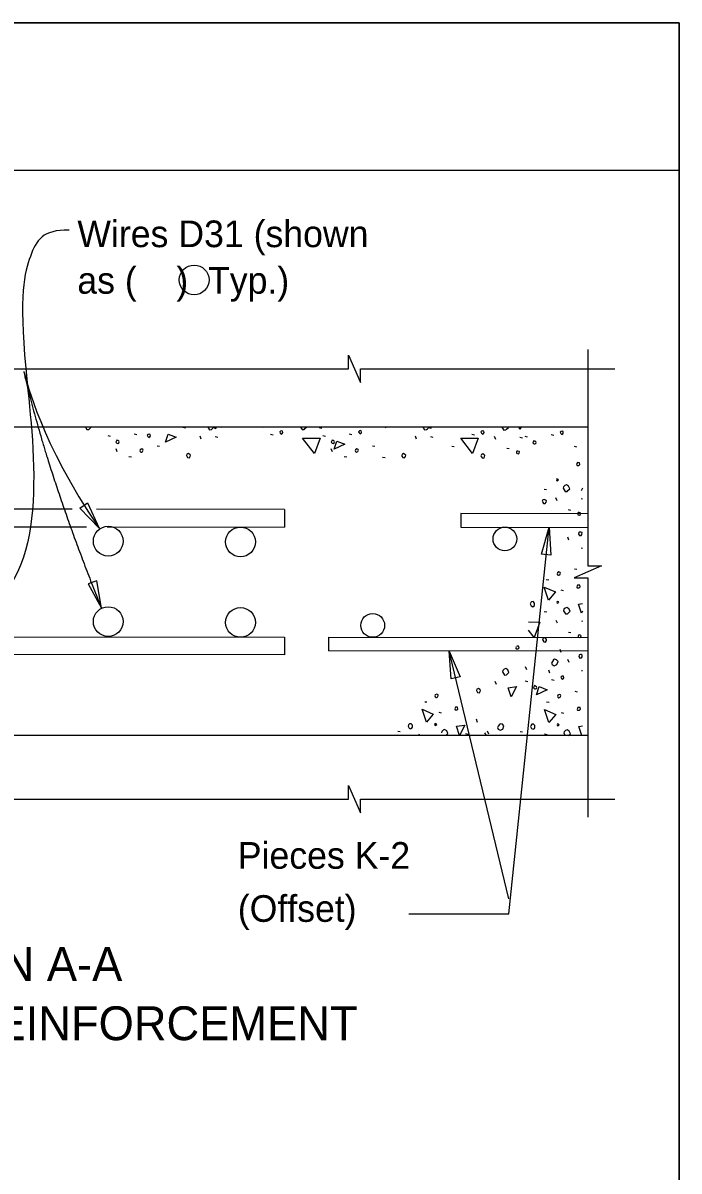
# Model space of a CAD drawing. Extents: x 0 to 20.5, y 0 to 13.
# Drawn here: x 18.052 to 20.533, y 8.632 to 12.973 of the extents above; entities that cross this region are included whole.
import ezdxf

# ---------------------------------------------------------------- set-up
doc = ezdxf.new("R2010")
doc.units = 0
for name, color, linetype in [('ActivePts-ConstElements', 7, 'Continuous'), ('BeamConc', 7, 'Continuous'), ('Dimension', 7, 'Continuous'), ('Miscellaneous', 7, 'Continuous'), ('Miscellaneous1', 7, 'Continuous'), ('Rebar', 7, 'Continuous'), ('Rebar_h', 7, 'Continuous')]:
    doc.layers.add(name, color=color, linetype=linetype)

msp = doc.modelspace()

# ---------------------------------------------------------------- linework, layer by layer
at = {"layer": 'ActivePts-ConstElements'}
msp.add_lwpolyline([(0, 0), (20.5333, 0), (20.5333, 12.9731), (0, 12.9731)], close=True, dxfattribs=at)
at = {"layer": 'BeamConc'}
for p, q in [((20.1882, 11.4449), (16.0404, 11.4449)), ((20.1882, 10.2782), (16.0404, 10.2782))]:
    msp.add_line(p, q, dxfattribs=at)
at = {"layer": 'Dimension'}
for p, q in [((0, 12.4165), (20.5333, 12.4165)), ((19.8892, 9.6606), (19.6674, 10.5821))]:
    msp.add_line(p, q, dxfattribs=at)
for points in [[(20.1882, 11.7379), (20.1882, 10.9199), (20.2398, 10.9199), (20.1882, 10.8974), (20.1365, 10.8749), (20.1882, 10.8749), (20.1882, 9.9704)], [(17.8713, 11.6648), (19.2832, 11.6648), (19.2832, 11.7165), (19.3057, 11.6648), (19.3282, 11.6131), (19.3282, 11.6648), (20.2903, 11.6648)], [(19.5119, 9.6044), (19.8892, 9.6044), (20.0416, 11.0659)], [(17.9336, 10.0376), (19.2832, 10.0376), (19.2832, 10.0893), (19.3057, 10.0376), (19.3282, 9.986), (19.3282, 10.0376), (20.2903, 10.0376)]]:
    msp.add_lwpolyline(points, dxfattribs=at)
for points in [[(18.2961, 11.1587), (18.3402, 11.0627), (18.267, 11.1388)], [(20.0132, 10.9641), (20.0416, 11.0659), (20.0483, 10.9605)], [(18.3492, 10.7599), (18.3317, 10.8641), (18.2984, 10.8525)], [(19.671, 10.4925), (19.6638, 10.5979), (19.7053, 10.5007)]]:
    msp.add_lwpolyline(points, close=True, dxfattribs=at)
for points, degree in [([(18.2263, 12.1894), (18.1269, 12.1921), (18.0784, 12.1111), (18.0162, 11.8657), (18.1616, 10.9078), (17.9075, 10.7552)], 3), ([(18.0553, 11.6549), (18.141, 11.2789), (18.3492, 10.7599)], 2), ([(18.0557, 11.6533), (18.0712, 11.6093), (18.1147, 11.3932), (18.3402, 11.0627)], 3)]:
    msp.add_open_spline(points, degree=degree, dxfattribs=at)
at = {"layer": 'Miscellaneous'}
for p, q in [((18.4453, 11.4435), (18.4448, 11.4449)), ((18.4724, 11.4188), (18.4824, 11.417)), ((18.6568, 11.4441), (18.6669, 11.4423)), ((18.9613, 11.4423), (18.9603, 11.4449)), ((18.9883, 11.4176), (18.9984, 11.4158)), ((19.1728, 11.4429), (19.1828, 11.4411)), ((19.2864, 11.4188), (19.2964, 11.417)), ((19.4244, 11.4411), (19.423, 11.4449)), ((19.7495, 11.4176), (19.7595, 11.4158)), ((18.3729, 11.4134), (18.3823, 11.4111)), ((18.5602, 11.3746), (18.569, 11.3728)), ((18.7264, 11.3993), (18.7222, 11.4105)), ((18.7792, 11.4093), (18.7887, 11.407)), ((19.1868, 11.4134), (19.1963, 11.4111)), ((19.3742, 11.3746), (19.383, 11.3728)), ((19.5404, 11.3993), (19.5362, 11.4105)), ((19.5932, 11.4093), (19.6027, 11.407)), ((19.84, 11.3981), (19.8359, 11.4093)), ((19.9314, 11.407), (19.9408, 11.4046)), ((19.9496, 11.4111), (19.959, 11.4087)), ((20.0492, 11.4164), (20.0592, 11.4146)), ((18.4082, 11.351), (18.4041, 11.3622)), ((18.4524, 11.3339), (18.463, 11.3327)), ((19.2222, 11.351), (19.2181, 11.3622)), ((19.2664, 11.3339), (19.277, 11.3327)), ((19.4114, 11.3315), (19.422, 11.3304)), ((19.6739, 11.3734), (19.6827, 11.3716)), ((19.8825, 11.3651), (19.8913, 11.3634)), ((20.137, 11.3722), (20.1458, 11.3704)), ((20.0227, 11.2108), (20.0327, 11.209)), ((20.0722, 11.166), (20.068, 11.1772)), ((20.1635, 11.1748), (20.1686, 11.1736)), ((20.1146, 11.133), (20.1234, 11.1312)), ((20.1169, 11.0175), (20.1122, 11.0293)), ((20.1629, 10.9881), (20.1686, 10.9873)), ((20.1381, 10.9091), (20.147, 10.9074)), ((20.0303, 10.8685), (20.0409, 10.8673)), ((20.0863, 10.829), (20.0957, 10.8266)), ((20.0239, 10.7477), (20.0339, 10.7459)), ((20.0734, 10.7029), (20.0692, 10.7141)), ((20.1647, 10.7118), (20.1686, 10.7108)), ((20.1158, 10.6699), (20.1246, 10.6682)), ((20.0881, 10.5927), (20.0834, 10.6045)), ((20.1181, 10.5545), (20.1134, 10.5662)), ((19.9578, 10.5266), (19.953, 10.5384)), ((20.0445, 10.5149), (20.0404, 10.5261)), ((20.1641, 10.525), (20.1686, 10.5244)), ((19.8424, 10.472), (19.8383, 10.4832)), ((19.952, 10.4849), (19.9614, 10.4825)), ((20.0515, 10.4902), (20.0615, 10.4885)), ((20.1393, 10.446), (20.1482, 10.4443)), ((19.5726, 10.4061), (19.579, 10.4054)), ((20.0315, 10.4054), (20.0421, 10.4042)), ((19.6244, 10.3671), (19.6338, 10.3647)), ((19.7717, 10.3282), (19.767, 10.34)), ((20.0875, 10.3659), (20.0969, 10.3635)), ((19.47, 10.2952), (19.4783, 10.294)), ((19.8135, 10.284), (19.8094, 10.2952)), ((19.9331, 10.294), (19.9414, 10.2929)), ((19.7254, 10.2858), (19.7354, 10.284)), ((20.025, 10.2846), (20.035, 10.2829))]:
    msp.add_line(p, q, dxfattribs=at)
for points in [[(18.2884, 11.4449), (18.2939, 11.4358), (18.3016, 11.4364), (18.3045, 11.4394), (18.31, 11.4449)], [(18.5247, 11.4091), (18.5283, 11.4056), (18.5318, 11.408), (18.5341, 11.4115), (18.533, 11.4174), (18.53, 11.418), (18.5259, 11.4174), (18.5224, 11.4139), (18.5247, 11.4091)], [(18.5914, 11.3881), (18.6008, 11.4187), (18.632, 11.4064), (18.5914, 11.3881)], [(18.7507, 11.4449), (18.757, 11.4347), (18.7647, 11.4353), (18.7676, 11.4382), (18.7741, 11.4447), (18.774, 11.4449)], [(18.7792, 11.4388), (18.7772, 11.4449)], [(18.7823, 11.4449), (18.7792, 11.4388)], [(18.7956, 11.444), (18.7953, 11.4449)], [(18.8014, 11.4449), (18.8001, 11.4423)], [(19.0255, 11.4217), (19.029, 11.4182), (19.0325, 11.4205), (19.0349, 11.4241), (19.0337, 11.4299), (19.0308, 11.4305), (19.0266, 11.4299), (19.0231, 11.4264), (19.0255, 11.4217)], [(19.1023, 11.4449), (19.1079, 11.4358), (19.1156, 11.4364), (19.1185, 11.4394), (19.124, 11.4449)], [(19.3235, 11.4229), (19.3271, 11.4193), (19.3306, 11.4217), (19.3329, 11.4252), (19.3318, 11.4311), (19.3288, 11.4317), (19.3247, 11.4311), (19.3212, 11.4276), (19.3235, 11.4229)], [(19.5647, 11.4449), (19.571, 11.4347), (19.5787, 11.4353), (19.5816, 11.4382), (19.5881, 11.4447), (19.588, 11.4449)], [(19.5932, 11.4388), (19.5912, 11.4449)], [(19.5963, 11.4449), (19.5932, 11.4388)], [(19.7866, 11.4217), (19.7901, 11.4182), (19.7937, 11.4205), (19.796, 11.4241), (19.7949, 11.4299), (19.7919, 11.4305), (19.7878, 11.4299), (19.7842, 11.4264), (19.7866, 11.4217)], [(19.8636, 11.4449), (19.8707, 11.4335), (19.8783, 11.4341), (19.8813, 11.437), (19.8878, 11.4435), (19.8872, 11.4449)], [(19.9313, 11.4364), (19.9286, 11.4449)], [(19.9357, 11.4449), (19.9313, 11.4364)], [(20.0863, 11.4205), (20.0898, 11.417), (20.0933, 11.4193), (20.0957, 11.4229), (20.0945, 11.4288), (20.0916, 11.4294), (20.0875, 11.4288), (20.0839, 11.4252), (20.0863, 11.4205)], [(18.407, 11.384), (18.4112, 11.3834), (18.4153, 11.3851), (18.4165, 11.3887), (18.4147, 11.3916), (18.4112, 11.394), (18.407, 11.3957), (18.4047, 11.391), (18.4035, 11.3875), (18.407, 11.384)], [(19.1545, 11.3445), (19.1097, 11.4034), (19.1763, 11.4028), (19.1545, 11.3445)], [(19.221, 11.384), (19.2252, 11.3834), (19.2293, 11.3851), (19.2305, 11.3887), (19.2287, 11.3916), (19.2252, 11.394), (19.221, 11.3957), (19.2187, 11.391), (19.2175, 11.3875), (19.221, 11.384)], [(19.2292, 11.3616), (19.2387, 11.3922), (19.2699, 11.3799), (19.2292, 11.3616)], [(19.7522, 11.3445), (19.7075, 11.4034), (19.774, 11.4028), (19.7522, 11.3445)], [(19.9838, 11.3816), (19.9879, 11.381), (19.992, 11.3828), (19.9932, 11.3863), (19.9914, 11.3893), (19.9879, 11.3916), (19.9838, 11.3934), (19.9814, 11.3887), (19.9802, 11.3851), (19.9838, 11.3816)], [(18.4977, 11.3498), (18.5001, 11.3498), (18.5048, 11.3522), (18.5066, 11.3575), (18.506, 11.3604), (18.5013, 11.3628), (18.4954, 11.3592), (18.4942, 11.3557), (18.4954, 11.3522), (18.4977, 11.3498)], [(18.6716, 11.3351), (18.6745, 11.3298), (18.6816, 11.3286), (18.6845, 11.3339), (18.6857, 11.3386), (18.6828, 11.3416), (18.6775, 11.3445), (18.6722, 11.3427), (18.6704, 11.3374), (18.6716, 11.3351)], [(19.3117, 11.3498), (19.3141, 11.3498), (19.3188, 11.3522), (19.3206, 11.3575), (19.32, 11.3604), (19.3153, 11.3628), (19.3094, 11.3592), (19.3082, 11.3557), (19.3094, 11.3522), (19.3117, 11.3498)], [(19.4856, 11.3351), (19.4885, 11.3298), (19.4956, 11.3286), (19.4985, 11.3339), (19.4997, 11.3386), (19.4968, 11.3416), (19.4915, 11.3445), (19.4862, 11.3427), (19.4844, 11.3374), (19.4856, 11.3351)], [(19.7852, 11.3339), (19.7882, 11.3286), (19.7953, 11.3274), (19.7982, 11.3327), (19.7994, 11.3374), (19.7964, 11.3404), (19.7911, 11.3433), (19.7858, 11.3416), (19.7841, 11.3363), (19.7852, 11.3339)], [(19.9184, 11.3457), (19.9249, 11.3439), (19.929, 11.3469), (19.9296, 11.351), (19.9284, 11.3522), (19.9237, 11.3545), (19.9196, 11.3539), (19.919, 11.3498), (19.9184, 11.3457)], [(20.1476, 11.3003), (20.1546, 11.3003), (20.1582, 11.3038), (20.1564, 11.3103), (20.1487, 11.3109), (20.1476, 11.3074), (20.1458, 11.3044), (20.1476, 11.3003), (20.1464, 11.3015)], [(20.0716, 11.242), (20.0781, 11.245), (20.0757, 11.2473), (20.0716, 11.2491), (20.0698, 11.245), (20.0716, 11.242)], [(20.0952, 11.2137), (20.1028, 11.2014), (20.1105, 11.2019), (20.1134, 11.2049), (20.1199, 11.2114), (20.1158, 11.2214), (20.1075, 11.2261), (20.1016, 11.2237), (20.0969, 11.219), (20.0952, 11.2137)], [(20.1686, 11.2142), (20.1635, 11.2043)], [(20.0174, 11.1619), (20.0203, 11.1566), (20.0274, 11.1554), (20.0303, 11.1608), (20.0315, 11.1655), (20.0286, 11.1684), (20.0233, 11.1714), (20.018, 11.1696), (20.0162, 11.1643), (20.0174, 11.1619)], [(20.1505, 11.1136), (20.157, 11.1118), (20.1612, 11.1147), (20.1617, 11.1189), (20.1606, 11.12), (20.1558, 11.1224), (20.1517, 11.1218), (20.1511, 11.1177), (20.1505, 11.1136)], [(20.1535, 11.0399), (20.1564, 11.0346), (20.1629, 11.0352), (20.1658, 11.0393), (20.1664, 11.0458), (20.1623, 11.0476), (20.1593, 11.0482), (20.1558, 11.047), (20.1546, 11.0458), (20.1535, 11.0399)], [(20.0757, 10.8844), (20.078, 10.8844), (20.0827, 10.8867), (20.0845, 10.892), (20.0839, 10.895), (20.0792, 10.8973), (20.0733, 10.8938), (20.0721, 10.8903), (20.0733, 10.8867), (20.0757, 10.8844)], [(20.0398, 10.7907), (20.0239, 10.8396), (20.0657, 10.8214), (20.0398, 10.7907)], [(20.1487, 10.8372), (20.1558, 10.8372), (20.1593, 10.8408), (20.1576, 10.8472), (20.1499, 10.8478), (20.1487, 10.8443), (20.147, 10.8414), (20.1487, 10.8372), (20.1476, 10.8384)], [(19.9708, 10.776), (19.9744, 10.7689), (19.9802, 10.7654), (19.985, 10.7689), (19.9873, 10.7725), (19.9873, 10.7795), (19.982, 10.7848), (19.9755, 10.7842), (19.9726, 10.7813), (19.9708, 10.776)], [(20.0728, 10.7789), (20.0792, 10.7819), (20.0769, 10.7842), (20.0728, 10.786), (20.071, 10.7819), (20.0728, 10.7789)], [(20.1646, 10.7412), (20.1535, 10.7759), (20.1686, 10.7779)], [(20.0963, 10.7506), (20.104, 10.7383), (20.1117, 10.7389), (20.1146, 10.7418), (20.1211, 10.7483), (20.117, 10.7583), (20.1087, 10.763), (20.1028, 10.7607), (20.0981, 10.756), (20.0963, 10.7506)], [(20.1686, 10.7488), (20.1646, 10.7412)], [(19.9646, 10.708), (20.0074, 10.7076), (19.9856, 10.6493)], [(19.9856, 10.6493), (19.9645, 10.677)], [(20.0186, 10.6387), (20.0215, 10.6334), (20.0286, 10.6322), (20.0315, 10.6375), (20.0327, 10.6422), (20.0297, 10.6452), (20.0244, 10.6481), (20.0191, 10.6463), (20.0174, 10.641), (20.0186, 10.6387)], [(20.1517, 10.6505), (20.1582, 10.6487), (20.1623, 10.6517), (20.1629, 10.6558), (20.1617, 10.657), (20.157, 10.6593), (20.1529, 10.6587), (20.1523, 10.6546), (20.1517, 10.6505)], [(19.918, 10.6141), (19.9178, 10.6134), (19.916, 10.6104), (19.9178, 10.6063), (19.9166, 10.6075)], [(19.9178, 10.6063), (19.9249, 10.6063), (19.9284, 10.6098), (19.9266, 10.6163), (19.9202, 10.6168)], [(20.0539, 10.5468), (20.0616, 10.5426), (20.0716, 10.5468), (20.0757, 10.5591), (20.0698, 10.565), (20.0622, 10.5668), (20.0586, 10.5644), (20.0545, 10.558), (20.0515, 10.5527), (20.0539, 10.5468)], [(20.1546, 10.5769), (20.1576, 10.5716), (20.1641, 10.5721), (20.167, 10.5763), (20.1676, 10.5827), (20.1635, 10.5845), (20.1605, 10.5851), (20.157, 10.5839), (20.1558, 10.5827), (20.1546, 10.5769)], [(19.8654, 10.5197), (19.873, 10.5073), (19.8807, 10.5079), (19.8836, 10.5109), (19.8901, 10.5173), (19.886, 10.5274), (19.8778, 10.5321), (19.8719, 10.5297), (19.8671, 10.525), (19.8654, 10.5197)], [(19.898, 10.4246), (19.8869, 10.4593), (19.9181, 10.4635), (19.898, 10.4246)], [(19.9861, 10.4554), (19.9903, 10.4548), (19.9944, 10.4566), (19.9956, 10.4601), (19.9938, 10.4631), (19.9903, 10.4654), (19.9861, 10.4672), (19.9838, 10.4625), (19.9826, 10.459), (19.9861, 10.4554)], [(19.9944, 10.4331), (20.0038, 10.4637), (20.035, 10.4513), (19.9944, 10.4331)], [(20.0886, 10.4944), (20.0922, 10.4908), (20.0957, 10.4932), (20.0981, 10.4967), (20.0969, 10.5026), (20.0939, 10.5032), (20.0898, 10.5026), (20.0863, 10.4991), (20.0886, 10.4944)], [(19.6138, 10.4225), (19.6161, 10.4225), (19.6208, 10.4248), (19.6226, 10.4301), (19.622, 10.4331), (19.6173, 10.4354), (19.6114, 10.4319), (19.6102, 10.4284), (19.6114, 10.4248), (19.6138, 10.4225)], [(19.7686, 10.4466), (19.7716, 10.4413), (19.7787, 10.4401), (19.7816, 10.4454), (19.7828, 10.4501), (19.7798, 10.4531), (19.7745, 10.456), (19.7692, 10.4542), (19.7675, 10.4489), (19.7686, 10.4466)], [(20.0769, 10.4213), (20.0792, 10.4213), (20.0839, 10.4236), (20.0857, 10.429), (20.0851, 10.4319), (20.0804, 10.4343), (20.0745, 10.4307), (20.0733, 10.4272), (20.0745, 10.4236), (20.0769, 10.4213)], [(19.5779, 10.3288), (19.562, 10.3777), (19.6038, 10.3595), (19.5779, 10.3288)], [(19.6868, 10.3753), (19.6939, 10.3753), (19.6974, 10.3789), (19.6957, 10.3853), (19.688, 10.3859), (19.6868, 10.3824), (19.6851, 10.3795), (19.6868, 10.3753), (19.6857, 10.3765)], [(20.0409, 10.3276), (20.025, 10.3765), (20.0669, 10.3583), (20.0409, 10.3276)], [(20.1499, 10.3742), (20.157, 10.3742), (20.1605, 10.3777), (20.1588, 10.3842), (20.1511, 10.3848), (20.1499, 10.3812), (20.1482, 10.3783), (20.1499, 10.3742), (20.1487, 10.3753)], [(19.5089, 10.3141), (19.5125, 10.307), (19.5183, 10.3035), (19.5231, 10.307), (19.5254, 10.3105), (19.5254, 10.3176), (19.5201, 10.3229), (19.5136, 10.3223), (19.5107, 10.3194), (19.5089, 10.3141)], [(19.6109, 10.317), (19.6173, 10.32), (19.615, 10.3223), (19.6109, 10.3241), (19.6091, 10.32), (19.6109, 10.317)], [(19.6521, 10.2793), (19.6527, 10.2799), (19.6592, 10.2864), (19.6551, 10.2964), (19.6468, 10.3011), (19.6409, 10.2988), (19.6362, 10.294), (19.6344, 10.2887)], [(19.7027, 10.2793), (19.6916, 10.314), (19.7228, 10.3182), (19.7027, 10.2793)], [(19.8492, 10.303), (19.8569, 10.2989), (19.8669, 10.303), (19.871, 10.3154), (19.8651, 10.3212), (19.8575, 10.323), (19.8539, 10.3207), (19.8498, 10.3142), (19.8469, 10.3089), (19.8492, 10.303)], [(19.972, 10.3129), (19.9755, 10.3058), (19.9814, 10.3023), (19.9861, 10.3058), (19.9885, 10.3094), (19.9885, 10.3164), (19.9832, 10.3217), (19.9767, 10.3212), (19.9738, 10.3182), (19.972, 10.3129)], [(20.0739, 10.3159), (20.0804, 10.3188), (20.0781, 10.3212), (20.0739, 10.3229), (20.0722, 10.3188), (20.0739, 10.3159)], [(20.1154, 10.2783), (20.1158, 10.2787), (20.1223, 10.2852), (20.1181, 10.2952), (20.1099, 10.2999), (20.104, 10.2976), (20.0993, 10.2929), (20.0975, 10.2876)], [(20.1658, 10.2782), (20.1546, 10.3129), (20.1686, 10.3147)], [(19.5508, 10.2834), (19.5481, 10.2782)], [(19.7978, 10.2887), (19.8037, 10.2793)], [(20.0975, 10.2876), (20.1032, 10.2783)]]:
    msp.add_lwpolyline(points, dxfattribs=at)
at = {"layer": 'Miscellaneous1'}
msp.add_lwpolyline([(0, 12.9731), (20.5333, 12.9731), (20.5333, 0), (0, 0)], close=True, dxfattribs=at)
at = {"layer": 'Rebar'}
for centre, radius in [((18.6995, 12.0012), 0.0563), ((18.3747, 11.0136), 0.0563), ((18.8748, 11.0105), 0.0563), ((19.8748, 11.0218), 0.045), ((18.3747, 10.7094), 0.0563), ((18.3747, 10.7094), 0.0563), ((18.8748, 10.7064), 0.0563), ((19.3748, 10.6951), 0.045)]:
    msp.add_circle(centre, radius, dxfattribs=at)
at = {"layer": 'Rebar_h'}
for p, q in [((19.0414, 11.1335), (19.0414, 11.0668)), ((19.7081, 11.1179), (19.7081, 11.0662)), ((17.5406, 11.0684), (18.2928, 11.0676)), ((18.3709, 11.0675), (19.0414, 11.0668)), ((19.7081, 11.0662), (20.1875, 11.0657)), ((16.2081, 10.6532), (19.0414, 10.6502)), ((19.0414, 10.6502), (19.0414, 10.5835)), ((19.2081, 10.65), (19.2081, 10.5983)), ((19.2081, 10.65), (20.1885, 10.6489)), ((20.1884, 10.5973), (19.2081, 10.5983)), ((19.0414, 10.5835), (16.2081, 10.5865))]:
    msp.add_line(p, q, dxfattribs=at)
for points in [[(18.2382, 11.1343), (17.5651, 11.1351)], [(19.0414, 11.1335), (18.3298, 11.1343)], [(20.1876, 11.1174), (19.7081, 11.1179)]]:
    msp.add_lwpolyline(points, dxfattribs=at)

# ---------------------------------------------------------------- texts
at = {"layer": 'Dimension'}
for s, height, p in [('Wires D31 (shown ', 0.1008, (18.2578, 12.1253)), ('as (    )  Typ.)', 0.1008, (18.2578, 11.9493)), ('Pieces K-2 ', 0.1008, (18.8646, 9.7749)), ('(Offset)', 0.1008, (18.8646, 9.5741)), ('SECTION A-A', 0.128, (17.3342, 9.3506)), ('FOR WELDED WIRE REINFORCEMENT', 0.128, (16.1416, 9.1266))]:
    msp.add_text(s, height=height, dxfattribs=at).set_placement(p)

doc.saveas('drawing.dxf')
